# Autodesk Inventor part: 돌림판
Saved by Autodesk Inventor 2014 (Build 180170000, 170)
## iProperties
Created: 2026-09
Part Number: 돌림판
Material: 일반
Document SubType Name: Modeling
Designer: dg
Density: 1 g/cm^3
Appearance: 기본값
Author: dg
Author: jhkim
Creation Date: 2026-08-27
Sending System: Autodesk Inventor 2027
Preprocessor: ST-DEVELOPER v20.1
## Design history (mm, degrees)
node "돌림판1"
node "솔리드1"
node "기준1"
